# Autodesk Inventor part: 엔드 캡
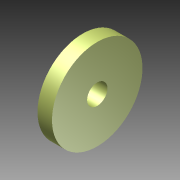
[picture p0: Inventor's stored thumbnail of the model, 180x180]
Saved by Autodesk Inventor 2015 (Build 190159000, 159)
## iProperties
Created: 2026-04
Part Number: 엔드 캡
Material: 일반
Document SubType Name: Modeling
Designer: User
Density: 1 g/cm^3
Appearance: 기본값
Author: User
Author: jhkim
Creation Date: 2026-03-26
Sending System: Autodesk Inventor 2026
Preprocessor: ST-DEVELOPER v20.1
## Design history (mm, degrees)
node "엔드 캡1"
node "솔리드1"
node "기준1"
